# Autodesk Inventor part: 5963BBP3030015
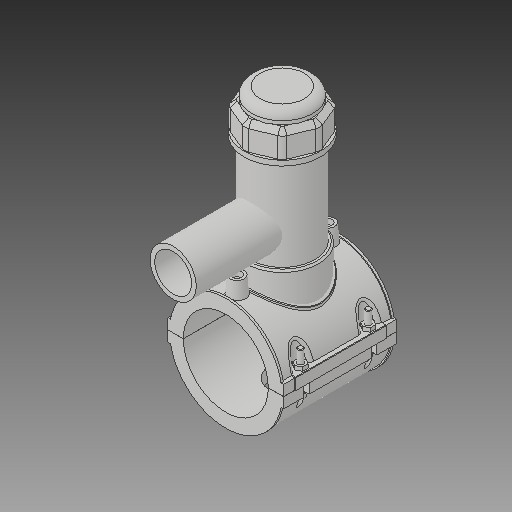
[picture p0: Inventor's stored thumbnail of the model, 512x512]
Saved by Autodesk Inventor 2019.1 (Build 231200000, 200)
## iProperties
Created: 2017-07
Part Number: 5963BBP3030015
Material: Generic
Description: PLASSON TAPPING SADDLE 3''IPS x 1 1/2''IPS
Document SubType Name: Modeling
Designer: KIM
Density: 1 g/cm^3
Appearance: Default
Author: KIM
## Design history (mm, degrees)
derived "5963BBP_5963BUP.ipt"
feature "Solid1::5963BBP_5963BUP.ipt"
feature "Solid2::5963BBP_5963BUP.ipt"
feature "Solid3::5963BBP_5963BUP.ipt"
tag "TaggingFeature1"
body "Solid1"
body "Solid2"
body "Solid3"
other parameters: "d0" = 88.7, "d2" = 120.904, "d3" = 22.175, "d4" = 118.11, "d5" = 0, "d6" = 0.1, "d8" = 0, "d19" = 6, "d20" = 6, "d21" = 70.866, "d23" = 0, "d24" = 35.433, "d26" = 0, "d27" = 3, "d28" = 3, "d29" = 3, "d30" = 29.56667, "d31" = 6, "d32" = 0, "d33" = 0, "d34" = 0.6, "d40" = 59.9612, "d41" = 79.83, "d43" = 0, "d45" = 0, "d47" = 128.521, "d70" = 15, "d72" = 0, "d73" = 6, "d75" = 5, "d76" = 0, "d77" = 4.435, "d78" = 74.35, "d79" = 15, "d80" = 47.244, "d82" = 5 deg, "d84" = 4, "d85" = 14, "d86" = 0, "d87" = 3, "d88" = 0, "d89" = 1, "d90" = 1, "d91" = 94.488, "d92" = 0, "d93" = 0.5, "d94" = 46.68421, "d96" = 117.6162, "d97" = 2.3622, "d98" = 0, "d102" = 0.887, "d120" = 140 deg, "d121" = 24.228, "d122" = 20 deg, "d123" = 230.62, "d124" = 69.186, "d126" = 0, "d143" = 91.361, "d145" = 20.46923, "d149" = 1.3305, "d150" = 22.51615, "d153" = 118.11, "d154" = 0, "d156" = 57.655, "d157" = 160 deg, "d159" = 5.322, "d161" = 1.3305, "d162" = 70.866, "d163" = 0, "d164" = 44.35, "d167" = 8.87, "d168" = 56.24878, "d170" = 3.2805, "d172" = 0, "d173" = 1, "d175" = 44.35, "d176" = 20 deg, "d177" = 6.209, "d178" = 26.61, "d180" = 0, "d183" = 10.644, "d184" = 4.9672, "d185" = 38.38575, "d186" = 38.38575, "d187" = 57.655, "d188" = 7.983, "d189" = 6.209, "d190" = 0, "d191" = 86.4825, "d193" = 6.9984, "d194" = 4.13385, "d195" = 90 deg, "d197" = 0, "d199" = 0, "d200" = 13.305, "d202" = 0, "d203" = 177.038, "d204" = 75.8385, "d205" = 55.881, "d206" = 67.8555, "d207" = 132.7785, "d208" = 138.08964, "d209" = 164.64534, "d210" = 68.6538, "d211" = 79.83, "d212" = 63.864, "d213" = 36.8766, "d216" = 0, "d217" = 8.87, "d218" = 8.87, "d219" = 1.774, "d222" = 88.7, "d224" = 0, "d225" = 65.024, "d226" = 48.1, "d227" = 38.48, "d228" = 114.046, "d230" = 5.322, "d_" = 88.7, "B_" = 120.904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
